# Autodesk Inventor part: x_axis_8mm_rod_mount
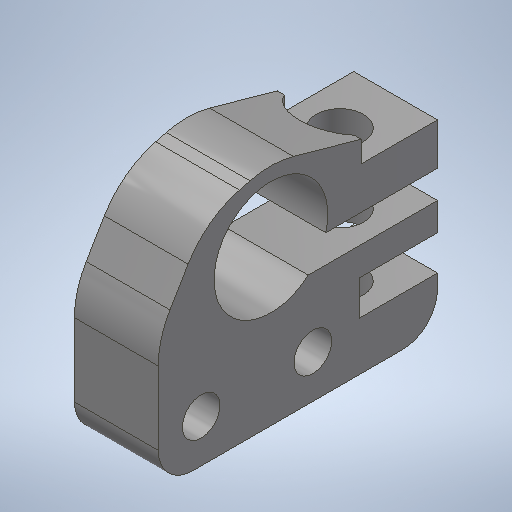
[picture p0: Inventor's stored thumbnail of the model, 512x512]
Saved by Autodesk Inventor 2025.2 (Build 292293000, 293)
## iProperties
Created: 2025-04
Part Number: x_axis_8mm_rod_mount
Material: 1.0037 S235JR
Document SubType Name: Modeling
Designer: BennF
Density: 7.85 g/cm^3
Appearance: Stahl
Author: BennF
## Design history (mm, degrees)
sketch "Sketch2"
  geometry: L1 (3.931, -1.075)-(11.931, -1.075); L2 (2.674, -3.075)-(11.931, -3.075); L3 (11.931, -3.075)-(11.931, -11.075); L4 (11.931, -11.075)-(-8.069, -11.075); L5 (-4.663, 4.046)-(0.061, 5.254); L6 (0.061, 5.254)-(11.931, 1.925); L7 (11.931, -1.075)-(11.931, 1.925); L8 (-4.663, 4.046)-(-8.069, -1.698); L9 (-8.069, -1.698)-(-8.069, -11.075); A1 r 4.075 centre (0, 0) between (3.931, -1.075) and (2.674, -3.075); 1 further point
  constraints: 18 end point, 3 vertical, 2 horizontal, 2 point on circle, 1 centre point, 1 coincident, 1 perpendicular, 1 vertical alignment
  dimensions: "d0" = 4.075 radius of A1; "d1" = 3 distance of L1.end L6.end; "d2" = 3.075 distance from line of point (0, 0) L2 (computed from d0); "d3" = 2 distance between parallel lines of L2 L1; "d4" = 5.075 distance from line of L6 A1.centre (computed from d0); "d5" = 5.075 distance from line of L5 point (0, 0) (= d4); "d6" = 8 distance of L1.start L1.end; "d7" = 150 deg angle of L6 L5; "d8" = 135 deg angle of L5 L8; "d9" = 6.075 distance from line of L8 point (0, 0) (computed from d4); "d10" = 20 distance of L3.end L4.end; "d11" = 8 distance of L2.end L3.end
extrude "Extrusion1" new body sketch "Sketch2" distance "d12" = 6; taper "d13" = 0 deg
workplane "Work Plane1"
sketch "Sketch3"
  geometry: L1 (0, 8)-(-6, 8) reference; L2 (0, 8)-(0, 0) reference; L3 (0, 0)-(-6, 0) reference; L4 (-6, 0)-(-6, 8) reference; L5 (-6, -11.631)-(-6, -7.861) reference; L6 (-6, -7.861)-(0, -7.861) reference; L7 (0, -7.861)-(0, -11.631) reference; L8 (-6, 8)-(0, 8) reference; L9 (0, -11.631)-(-6, -11.631) reference; 4 further points
  constraints: 2 midpoint, 1 horizontal alignment, 1 vertical alignment
hole "Hole1" sketch "Sketch3" at (-3, 4) diameter "d15" = 3.4; stored, may be unused: countersink angle "d19" = 90 deg, drill point angle "d21" = 118 deg; dims "d16" = 6, "d17" = 7.5, "d18" = 2, "d20" = 8
workplane "Work Plane2"
sketch "Sketch4"
  geometry: L1 (-3.523, 6.231)-(1.075, 6.231) reference; L2 (-2.57, 9.631)-(1.075, 9.631) reference; L3 (-3.86, 5.031)-(-1.925, 5.031); L4 (-1.925, 5.031)-(-1.925, 7.931); L5 (-1.925, 7.931)-(-3.86, 7.931); L6 (-3.86, 7.931)-(-3.86, 5.031); L7 (1.075, 9.631)-(1.075, 6.231) reference; L8 (-1.925, 11.931)-(-5.254, 0.061) reference; 2 further points
  constraints: 8 end point, 2 parallel, 1 horizontal, 1 horizontal alignment, 1 midpoint, 1 perpendicular, 1 point on line
  dimensions: "d22" = 3 distance between parallel lines of L7 L4; "d23" = 5.8 diameter of L3 L5
revolve "Revolution1" sketch "Sketch4" stored, may be unused: angle "d24" = 90 deg
sketch "Sketch5"
  geometry: C1 r 1.7 at (3, 5.257) reference; 2 further points
  constraints: 1 coincident
hole "Hole2" sketch "Sketch5" at (3, 5.257) diameter "d25" = 3.4; stored, may be unused: countersink angle "d29" = 90 deg, drill point angle "d31" = 0 deg; dims "d26" = 6, "d27" = 4, "d28" = 2, "d30" = 5
workplane "Work Plane3"
sketch "Sketch6"
  geometry: L1 (3, 2.081)-(0.25, 3.669); L2 (0.25, 3.669)-(0.25, 6.844); L3 (0.25, 6.844)-(3, 8.432); L4 (3, 8.432)-(5.75, 6.844); L5 (5.75, 6.844)-(5.75, 3.669); L6 (5.75, 3.669)-(3, 2.081); L7 (0, 9.257)-(6, 9.257) reference; L8 (5.75, 3.669)-(6, 3.669); L9 (6, -10.743)-(6, 9.257) reference; L10 (0.25, 3.669)-(0, 3.669); L11 (0, -10.743)-(0, 9.257) reference; 3 further points
  constraints: 16 end point, 2 horizontal, 2 point on line, 1 coincident, 1 vertical alignment, 13 other
  dimensions: "d33" = 5.5 distance between parallel lines of L2 L5
extrude "Extrusion2" cut sketch "Sketch6" distance "d34" = 2.5; taper "d35" = 0 deg
sketch "Sketch7"
  geometry: L1 (8, -5)-(8, 3); L2 (11.075, -8.069)-(11.075, 11.931) reference; L3 (1.698, -8.069)-(11.075, -8.069) reference; 1 further point
  constraints: 2 end point, 1 vertical, 1 vertical alignment
  dimensions: "d43" = 8 distance of L1.start L1.end; "d53" = 5 vertical distance of point (0, 0) L1.start; "d58" = 8 distance from line of L1 point (0, 0)
hole "Hole3" sketch "Sketch7" at (8, -5), (8, 3) diameter "d36" = 2.7; stored, may be unused: countersink angle "d40" = 90 deg, drill point angle "d42" = 0 deg; dims "d37" = 6 (= d12), "d38" = 4, "d39" = 2, "d41" = 5
fillet "Fillet1" dims "d46" = 6
sketch "Sketch8"
  geometry: L1 (3, -4)-(3, 4) reference; L2 (-3, -4)-(-3, 4) reference; L3 (-3, 4)-(3, 4) reference; L4 (2.5, -1.47)-(3, -1.47); L5 (-2.5, -1.47)-(-3, -1.47); A1 r 2.9 centre (0, 0) between (2.5, -1.47) and (-2.5, -1.47) reference; A2 r 2.9 centre (0, 0) between (2.5, -1.47) and (-2.5, -1.47); 1 further point
  constraints: 5 point on circle, 4 end point, 3 point on line, 1 centre point, 1 coincident, 1 collinear, 1 concentric, 1 horizontal alignment, 1 perpendicular
  dimensions: "d56" = 0.5 distance of L4.start L4.end
extrude "Extrusion3" cut sketch "Sketch8" extent not by distance; stored distance "d54" = 0; taper "d55" = 0 deg
fillet "Fillet2" dims "d57" = 2.5
body "Solid1"
node "Project Cut Edges1"
other parameters: "d14" = -2, "d32" = -2
